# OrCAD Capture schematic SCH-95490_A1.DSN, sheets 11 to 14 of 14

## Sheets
11 11 QSPI FLASH & SENSOR: size C
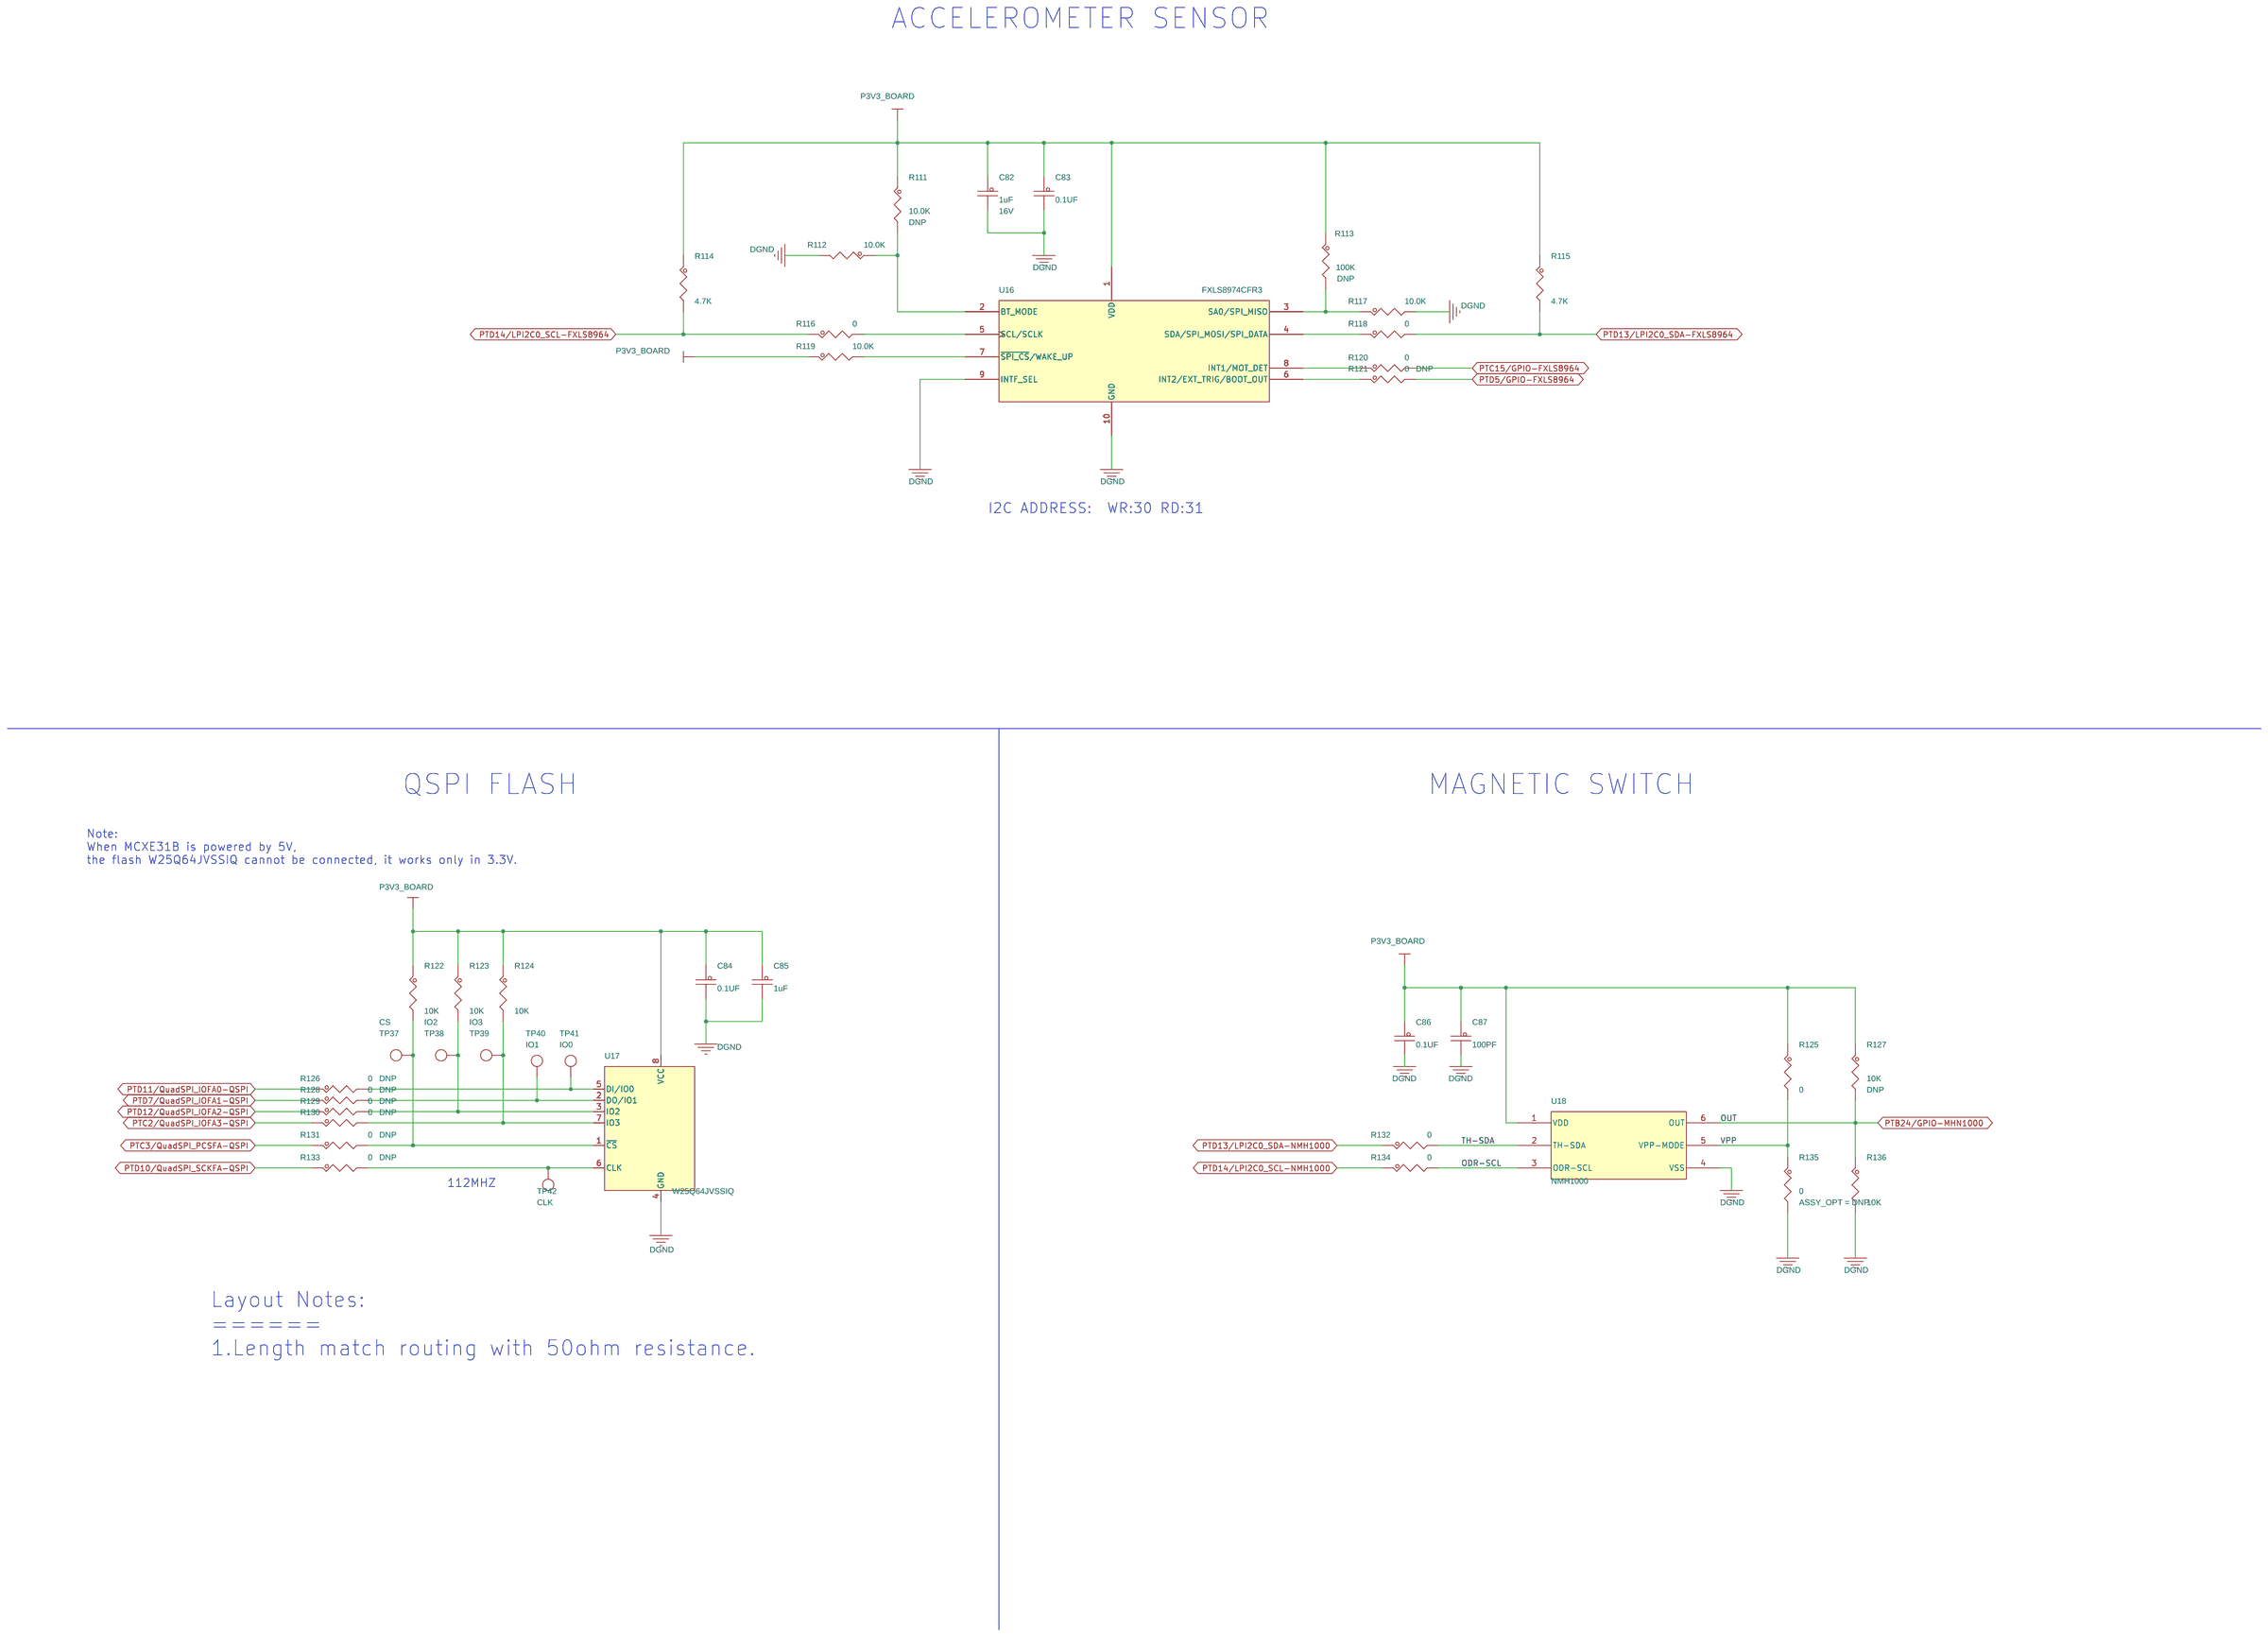
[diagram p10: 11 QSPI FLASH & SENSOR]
12 12 SWITCH & LED: size C
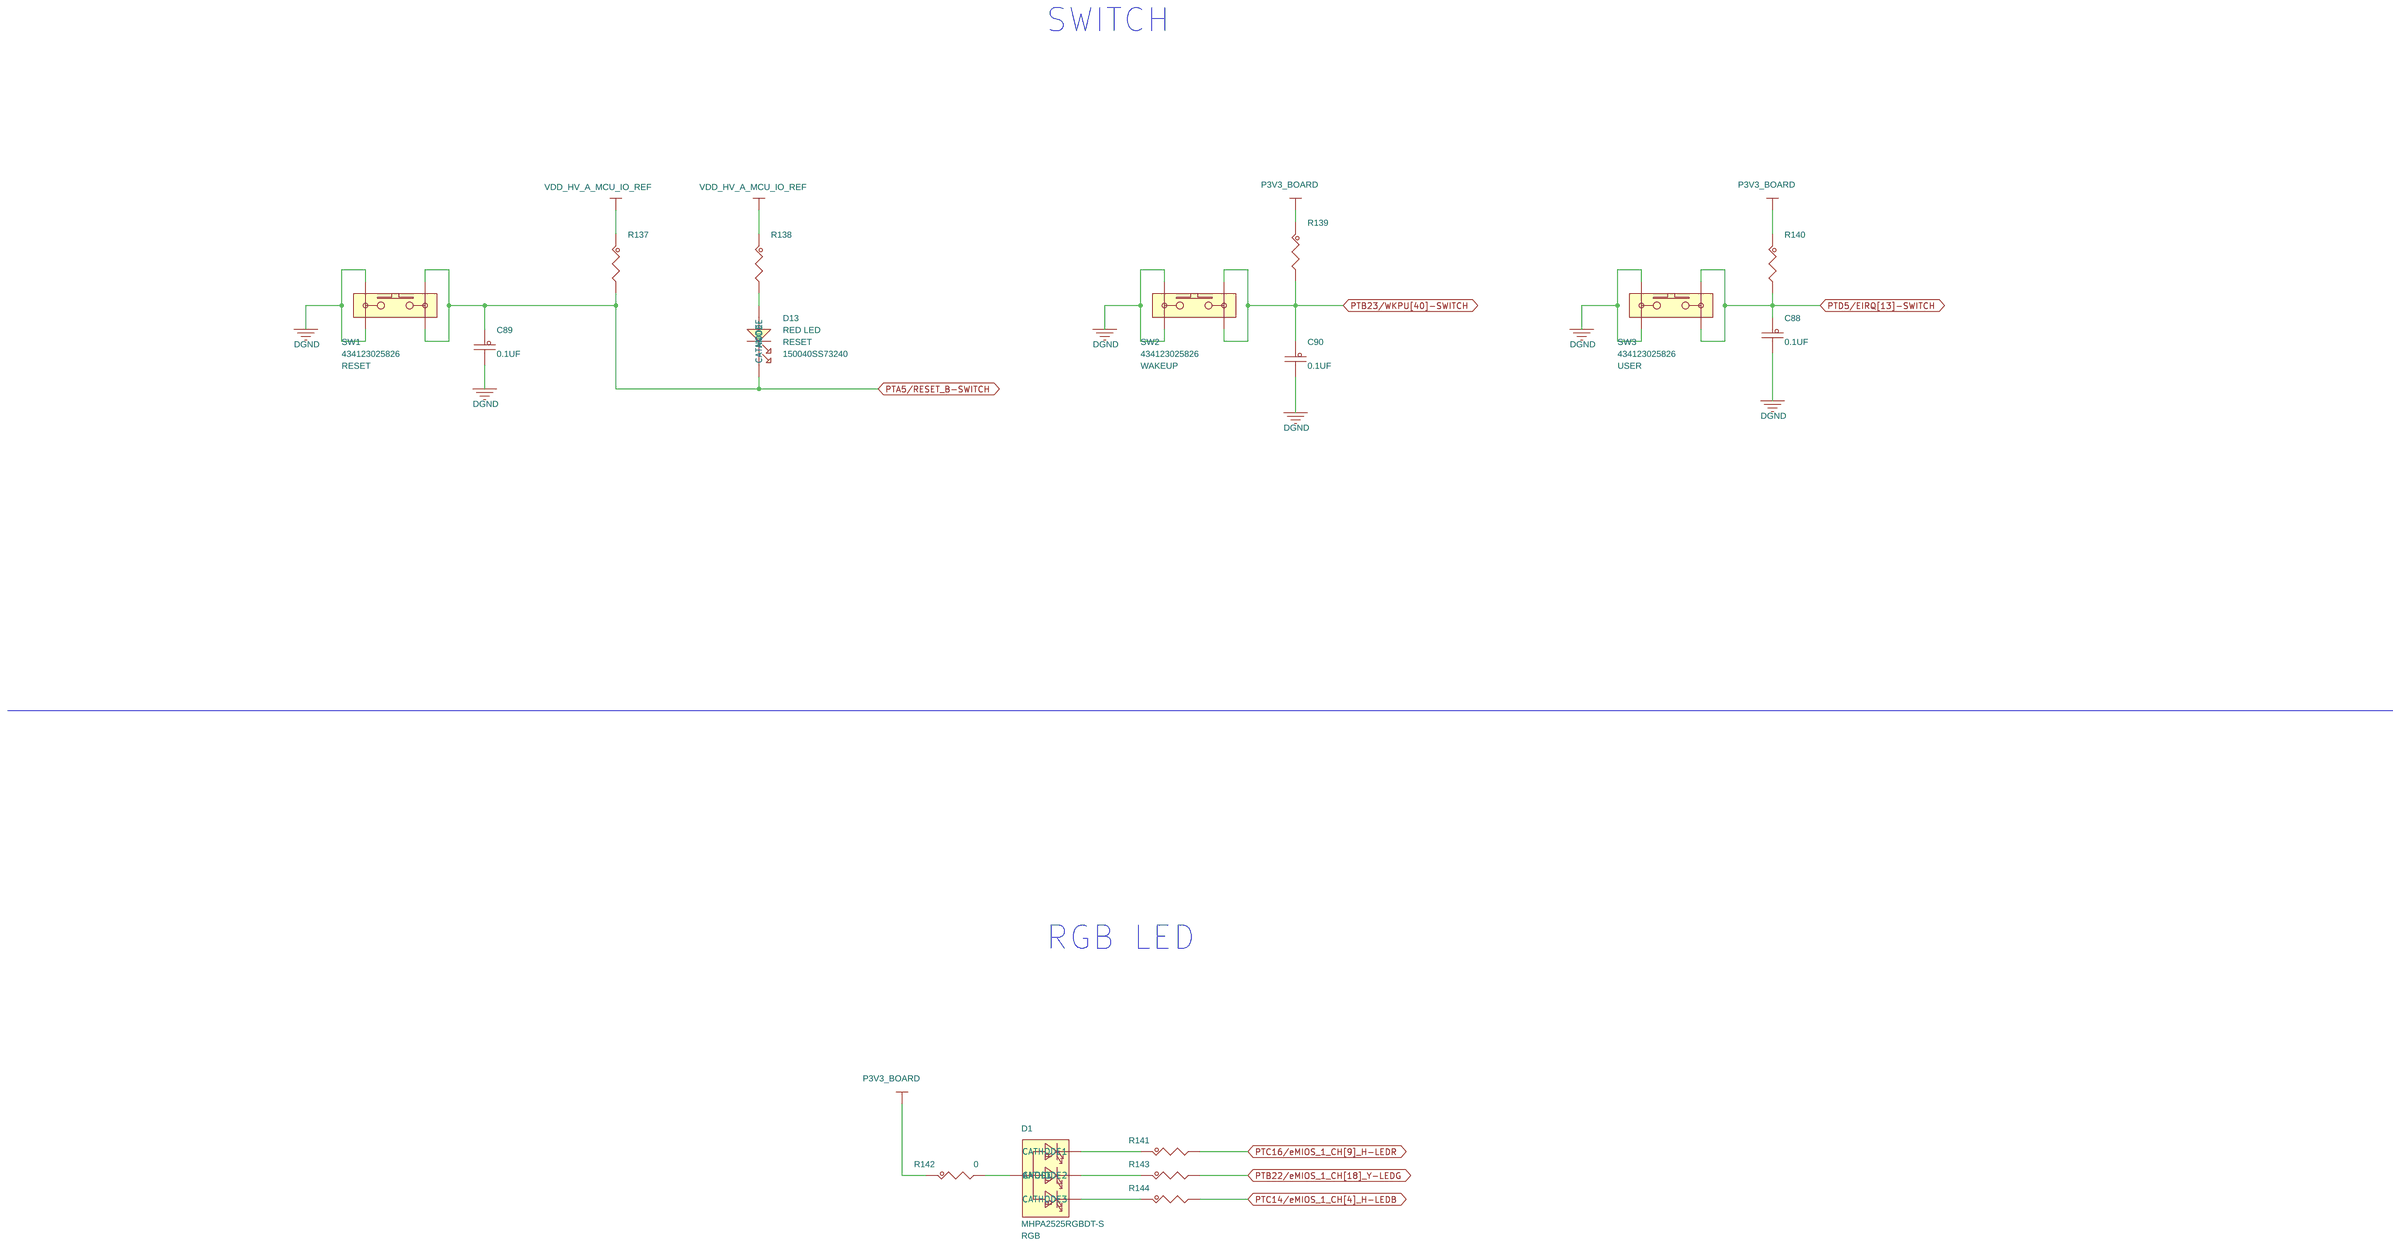
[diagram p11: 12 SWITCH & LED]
13 13 HEADERS: size C
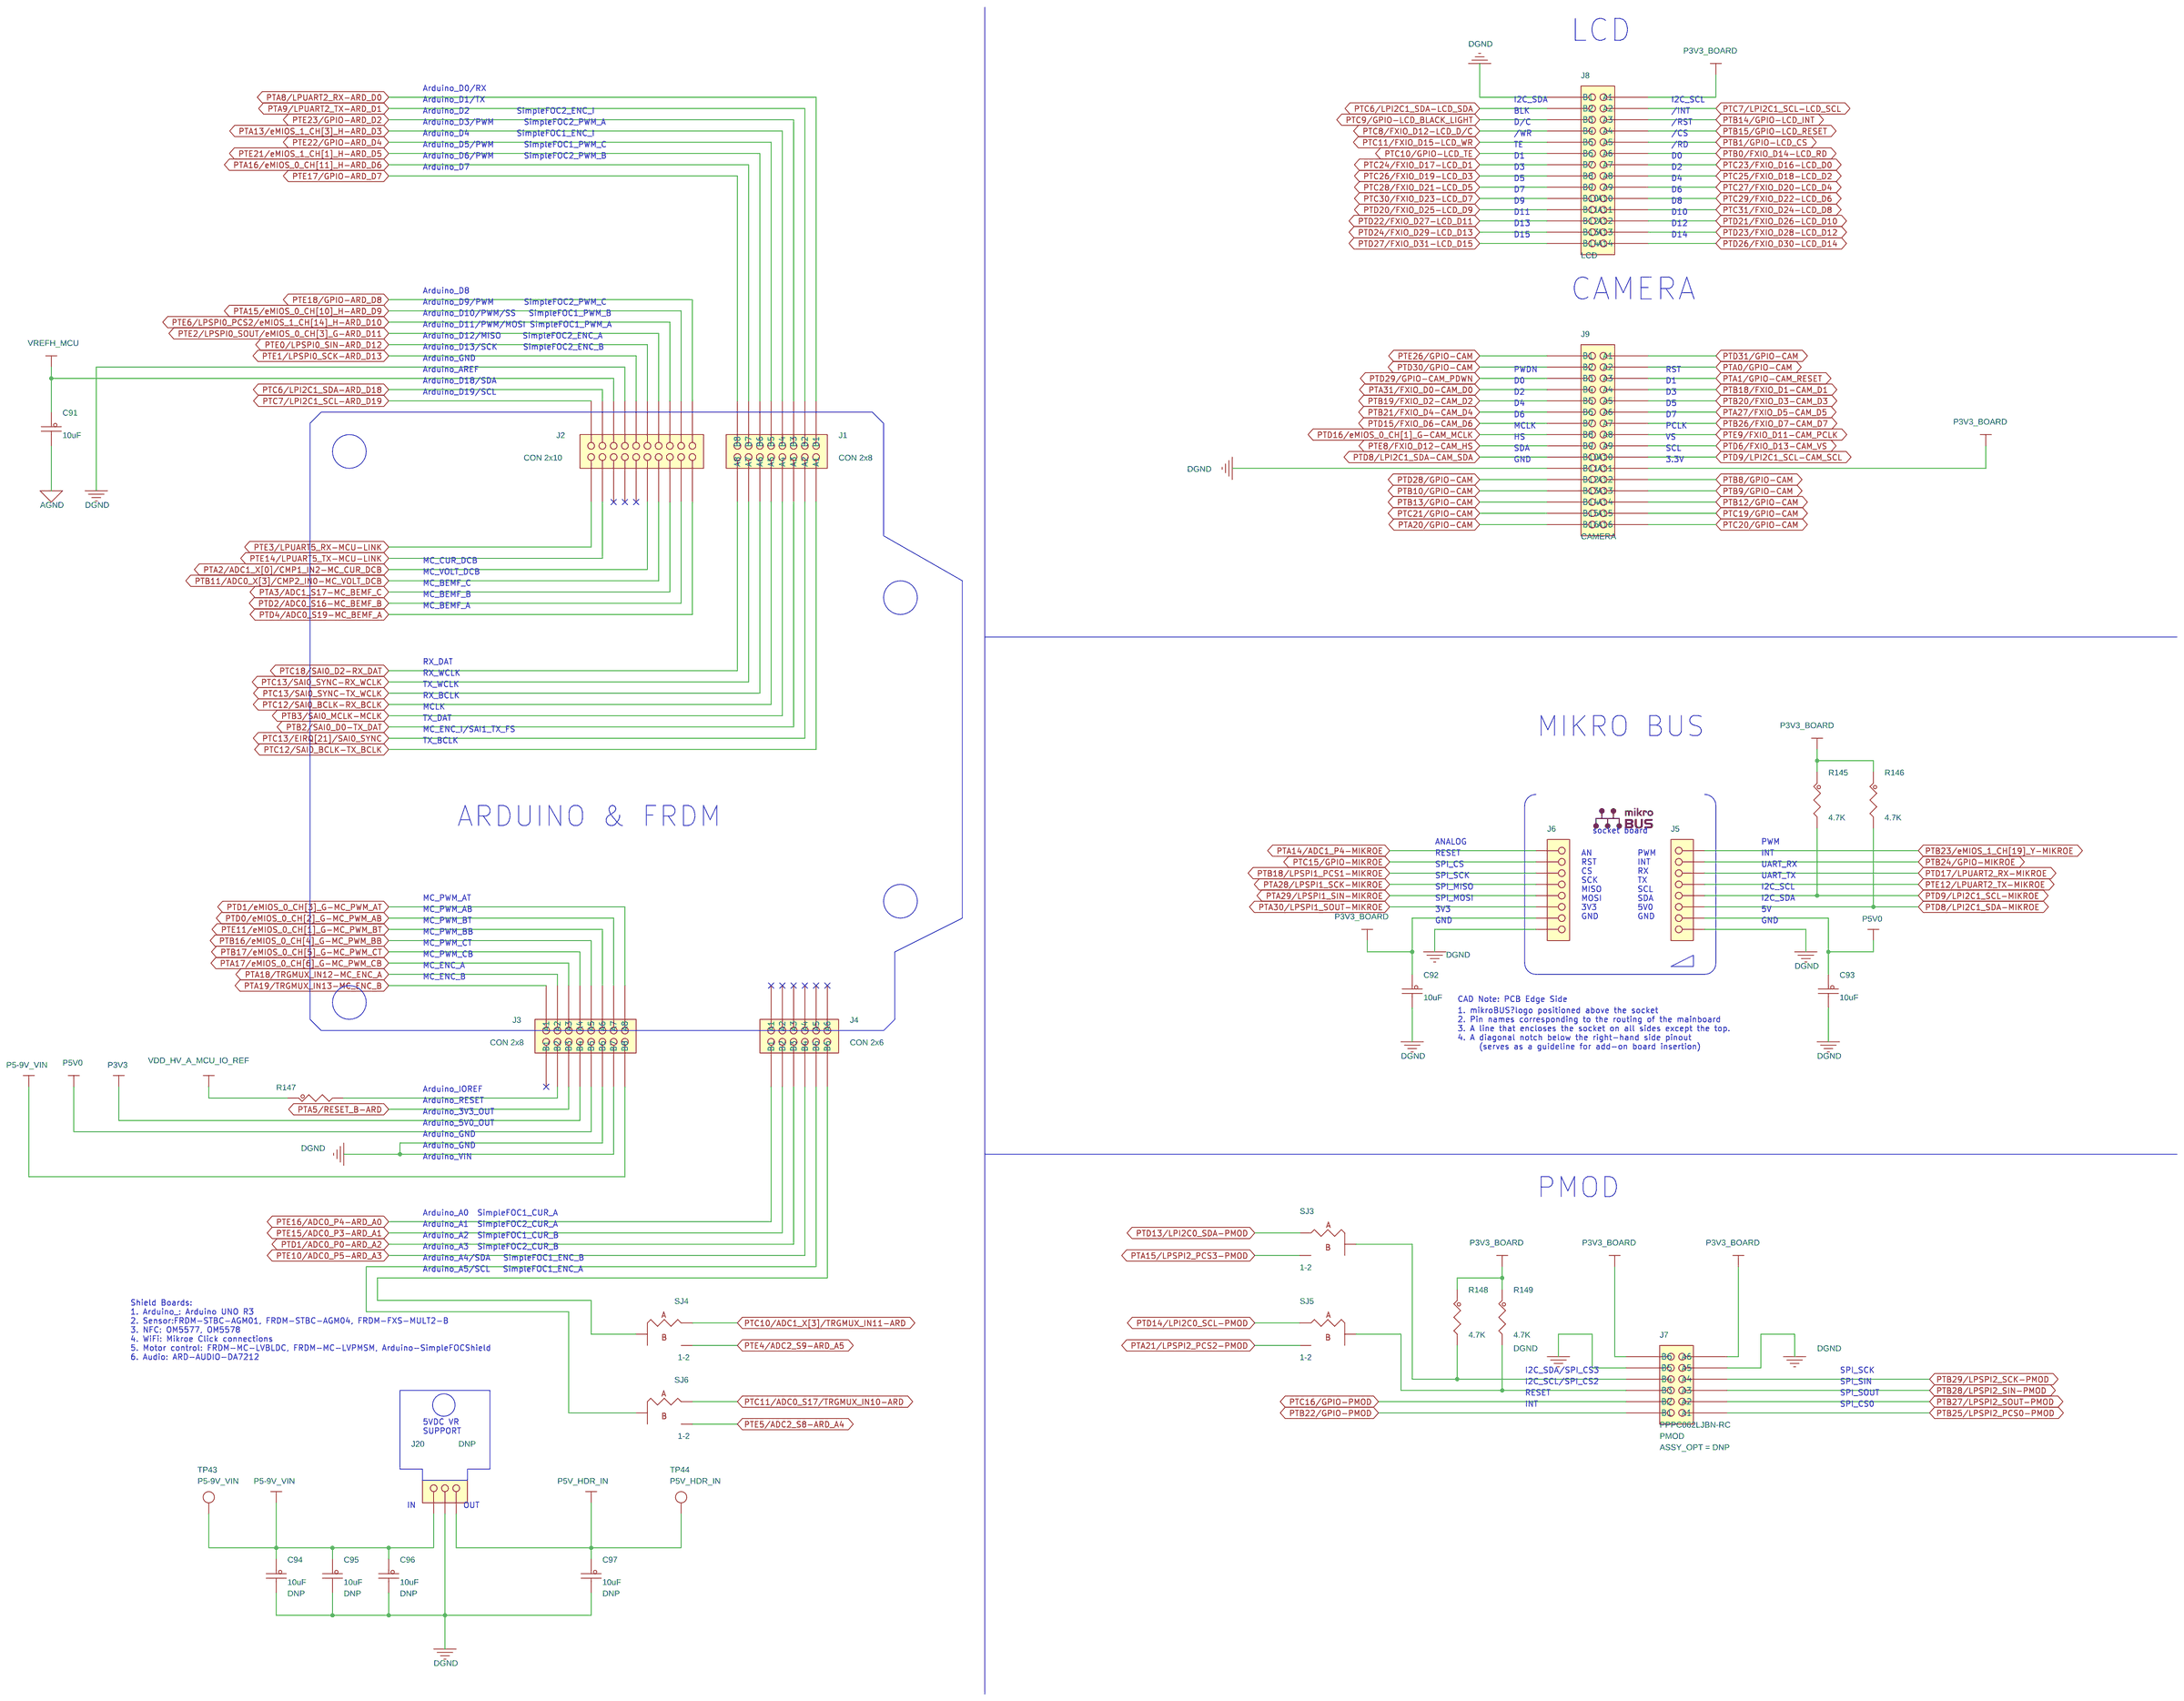
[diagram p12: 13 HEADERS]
14 14 APPENDIX JUMPER/DNP
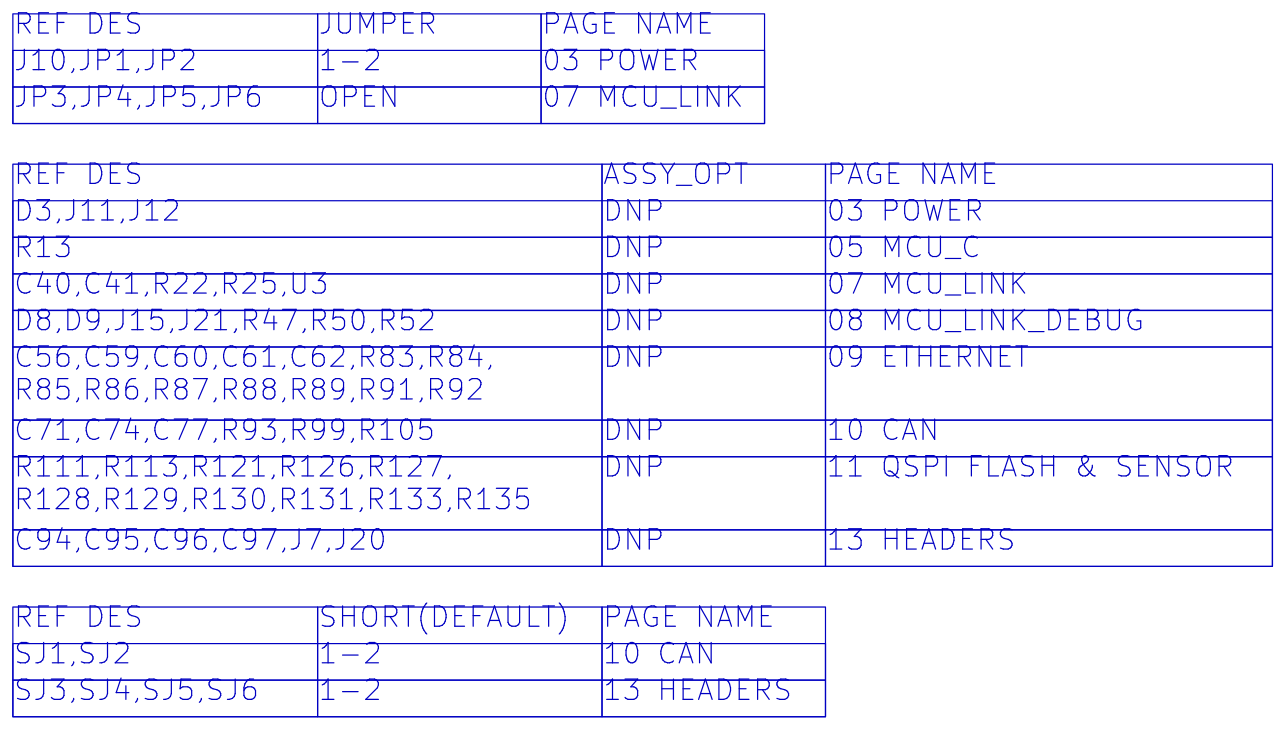
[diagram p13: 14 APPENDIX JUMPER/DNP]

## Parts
sheet 11 QSPI FLASH & SENSOR
C82  1uF  [CC0402_25]
C83  0.1UF  [CC0402_25]
C84  0.1UF  [CC0402_25]
C85  1uF  [CC0402_25]
C86  0.1UF  [CC0402_25]
C87  100PF  [CC0402_25]
R111  10.0K  [RC0402_25]
R112  10.0K  [RC0402_25]
R113  100K  [RC0402_25]
R114  4.7K  [RC0402_25]
R115  4.7K  [RC0402_25]
R116  0  [RC0603_OV]
R117  10.0K  [RC0402_25]
R118  0  [RC0603_OV]
R119  10.0K  [RC0402_25]
R120  0  [RC0603_OV]
R121  0  [RC0603_OV]
R122  10K  [RC0402_25]
R123  10K  [RC0402_25]
R124  10K  [RC0402_25]
R125  0  [RC0603_OV]
R126  0  [RC0603_OV]
R127  10K  [RC0402_25]
R128  0  [RC0603_OV]
R129  0  [RC0603_OV]
R130  0  [RC0603_OV]
R131  0  [RC0603_OV]
R132  0  [RC0603_OV]
R133  0  [RC0603_OV]
R134  0  [RC0603_OV]
R135  0  [RC0603_OV]
R136  10K  [RC0402_25]
TP37  TPAD_030  [TPAD_030]
TP38  TPAD_030  [TPAD_030]
TP39  TPAD_030  [TPAD_030]
TP40  TPAD_030  [TPAD_030]
TP41  TPAD_030  [TPAD_030]
TP42  TPAD_030  [TPAD_030]
U16  FXLS8974CFR3  [DFN_10_0P4_2X2]
U17  W25Q64JVSSIQ  [so8_w]
U18  NMH1000  [dfn6_0p5_1p4sq]
sheet 12 SWITCH & LED
C88  0.1UF  [CC0402_25]
C89  0.1UF  [CC0402_25]
C90  0.1UF  [CC0402_25]
D1  RGB  [led4_2p7x2p6_sm]
D13  RED LED  [led_1p1_1p1x0p6_sm]
R137  10K  [RC0402_25]
R138  470  [RC0402_25]
R139  10K  [RC0402_25]
R140  10K  [RC0402_25]
R141  470  [RC0402_25]
R142  0  [RC0603_OV]
R143  470  [RC0402_25]
R144  470  [RC0402_25]
SW1  SW SPST NO  [sw4_4p15_4p2x3p2_sm]
SW2  SW SPST NO  [sw4_4p15_4p2x3p2_sm]
SW3  SW SPST NO  [sw4_4p15_4p2x3p2_sm]
sheet 13 HEADERS
C91  10uF  [CC0603_OV]
C92  10uF  [CC0603_OV]
C93  10uF  [CC0603_OV]
C94  10uF  [CC0603_OV]
C95  10uF  [CC0603_OV]
C96  10uF  [CC0603_OV]
C97  10uF  [CC0603_OV]
J1  CON 2x8  [con_2x8_skt_100_th]
J2  CON 2x10  [con_skt2x10_th]
J3  CON 2x8  [con_2x8_skt_100_th]
J4  CON 2x6  [con_skt2x6_th_126l]
J5  SKT_1X8  [con_1x8_skt_2p54_th_126l]
J6  SKT_1X8  [con_1x8_skt_2p54_th_126l]
J7  PPPC062LJBN-RC  [skt2x6_100_th_ra]
J8  CON 2x14  [con_skt2x14_th_126l]
J9  CON 2x16  [con_skt_32f_100_th]
J20  HDR_1X3  [HDR103]
R145  4.7K  [RC0402_25]
R146  4.7K  [RC0402_25]
R147  470  [RC0402_25]
R148  4.7K  [RC0402_25]
R149  4.7K  [RC0402_25]
SJ3  3 PIN 0402 JUMPER  [3pin_0402x2_a]
SJ4  3 PIN 0402 JUMPER  [3pin_0402x2_a]
SJ5  3 PIN 0402 JUMPER  [3pin_0402x2_a]
SJ6  3 PIN 0402 JUMPER  [3pin_0402x2_a]
TP43  TEST POINT  [tpad_040-fct]
TP44  TEST POINT  [tpad_040-fct]

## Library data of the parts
C82 C85 = CAP_NP: CAP CER 1.0uF 16V 10% X6S 0402; AGILE_PN: 150-80262; CAD_APPROVED: Yes; FPLIST: CC0402_25,CC0402_HD,0402_CC,capc0402_l; HEIGHT: 0.55; MFG_NAME01: MURATA; MFG_PN01: GRM155C81C105KE11D; ROHS: Yes; Rated Voltage: 16V; Temp Range: -55C to +105C; Tolerance: 10%; VOLTAGE: 16V
C83 C84 C86 C88-C90 = CAP_NP: CAP CER 0.1UF 16V 10% X7R 0402; 3D_Mechanical_Footprint_File: http://fcl.am.freescale.net/ALLEGRO/step/cc0402_25.STEP; AGILE_PN: 150-75182; CAD_APPROVED: Yes; FPLIST: CC0402_25,CC0402_HD,0402_CC,CAPC0402_L,cc0402_lamp3; HEIGHT: 0.635mm; MFG_NAME01: Samsung Electro-Mechanics; MFG_PN01: CL05B104KO5NNNC; ROHS: NULL; Rated Voltage: 16V; SIGNAL_MODEL: DEFAULT_CAPACITOR_100000pF_2_1; TOL: 10%; Temp Range: -55C to +125C; Temp_Range: -55°C to +85°C; Tolerance: 10%; VOLTAGE: 16V
C87 = CAP_NP: CAP CER 100pF 16V 10% X7R 0402; AGILE_PN: 150-79188; CAD_APPROVED: Yes; FPLIST: CC0402_25,CC0402_HD,0402_CC,capc0402_l; HEIGHT: 0.56; MFG_NAME01: AVX; MFG_PN01: 0402YC101KAT2A; Package Size: 0402; Package Type: 7" Reel; ROHS: Yes; Rated Voltage: 16V; TOL: 5%; Temp Range: -55C to +125C; Tolerance: 10%; VOLTAGE: 50V
R111 = RES: RES MF 10.0K 1/16W 1% 0402; AGILE_PN: 470-80574; ASSY_OPT: DNP; CAD_APPROVED: Yes; FPLIST: RC0402_25,RC0402_HD,0402_CC; HEIGHT: 0.4; MFG_NAME01: BOURNS; MFG_PN01: CR0402-FX-1002GLF; ROHS: Yes; Tolerance: 1%
R112 R117 R119 = RES: RES MF 10.0K 1/16W 1% 0402; AGILE_PN: 470-80574; CAD_APPROVED: Yes; FPLIST: RC0402_25,RC0402_HD,0402_CC; HEIGHT: 0.4; MFG_NAME01: BOURNS; MFG_PN01: CR0402-FX-1002GLF; ROHS: Yes; Tolerance: 1%
R113 = RES: RES MF 100K 1/16W 1% 0402; AGILE_PN: 470-76240; ASSY_OPT: DNP; CAD_APPROVED: Yes; FPLIST: RC0402_25,RC0402_HD,0402_CC; HEIGHT: 0.4; MFG_NAME01: VISHAY INTERTECHNOLOGY; MFG_PN01: CRCW0402100KFKEDC; ROHS: Yes; Tolerance: 1%
R114 R115 R145 R146 R148 R149 = RES: RES MF 4.7K 1/16W 5% 0402; AGILE_PN: 470-75626; CAD_APPROVED: Yes; FPLIST: RC0402_25,RC0402_HD,0402_CC,RC0402_X2; HEIGHT: 0.41; MFG_NAME01: BOURNS; MFG_PN01: CR0402-JW-472GLF; Pkg: 0402; ROHS: NULL; Tolerance: 5%
R116 R118 R120 R125 R132 R134 = RES: RES MF ZERO OHM 1/10W -- 0603; AGILE_PN: 470-80866; CAD_APPROVED: Yes; FPLIST: RC0603_OV,RC0603,R603-X2,r603-x2_b,0603_CC,IND_0603HP_NSP,CC0603_OV_NSP; HEIGHT: 0.6; MFG_NAME01: VISHAY; MFG_PN01: CRCW06030000Z0EAC; ROHS: NULL; Temp Range: –55 °C to +155 °C; VOLTAGE: 1/16W
R121 R135 = RES: RES MF ZERO OHM 1/10W -- 0603; AGILE_PN: 470-80866; ASSY_OPT: DNP; CAD_APPROVED: Yes; FPLIST: RC0603_OV,RC0603,R603-X2,r603-x2_b,0603_CC,IND_0603HP_NSP,CC0603_OV_NSP; HEIGHT: 0.6; MFG_NAME01: VISHAY; MFG_PN01: CRCW06030000Z0EAC; ROHS: NULL; Temp Range: –55 °C to +155 °C; VOLTAGE: 1/16W
R122-R124 = RES: RES MF 10K 1/16W 5% 0402; AGILE_PN: 470-75557; CAD_APPROVED: Yes; FPLIST: RC0402_25,RC0402_HD,0402_CC; HEIGHT: 0.4MM; MFG_NAME01: BOURNS; MFG_PN01: CR0402-JW-103GLF; ROHS: NULL; SIGNAL_MODEL: DEFAULT_RESISTOR_10000OHM_2_1; TOL: 1%; Temp_Range: –55 °C to +155 °C; Tolerance: 5%
R126 R128-R131 R133 = RES: RES MF ZERO OHM 1/10W -- 0603; AGILE_PN: 470-80866; ASSY_OPT: DNP; CAD_APPROVED: Yes; FPLIST: RC0603_OV,RC0603,R603-X2,r603-x2_b,0603_CC,IND_0603HP_NSP,CC0603_OV_NSP; HEIGHT: 0.6; MFG_NAME01: VISHAY; MFG_PN01: CRCW06030000Z0EAC; ROHS: NULL; Temp Range: –55 °C to +155 °C
R127 = RES: RES MF 10K 1/16W 5% 0402; AGILE_PN: 470-75557; ASSY_OPT: DNP; CAD_APPROVED: Yes; FPLIST: RC0402_25,RC0402_HD,0402_CC; HEIGHT: 0.4MM; MFG_NAME01: BOURNS; MFG_PN01: CR0402-JW-103GLF; ROHS: NULL; Tolerance: 5%
R136 = RES: RES MF 10K 1/16W 5% 0402; AGILE_PN: 470-75557; CAD_APPROVED: Yes; FPLIST: RC0402_25,RC0402_HD,0402_CC; HEIGHT: 0.4MM; MFG_NAME01: BOURNS; MFG_PN01: CR0402-JW-103GLF; ROHS: NULL; Tolerance: 5%
TP37 = TESTLOOP: TEST POINT PAD 30MIL DIA SMT, NO PART TO ORDER; 3D_Mechanical_Footprint_File: http://fcl.am.freescale.net/ALLEGRO/step/tpad_030.STEP; AGILE_PN: 211-76642; CAD_APPROVED: Yes; HEIGHT: 0.1; MFG_NAME01: NOTACOMPONENT; MFG_PN01: NOTACOMPONENT; ROHS: Yes; SILK: CS
TP38 = TESTLOOP: TEST POINT PAD 30MIL DIA SMT, NO PART TO ORDER; 3D_Mechanical_Footprint_File: http://fcl.am.freescale.net/ALLEGRO/step/tpad_030.STEP; AGILE_PN: 211-76642; CAD_APPROVED: Yes; HEIGHT: 0.1; MFG_NAME01: NOTACOMPONENT; MFG_PN01: NOTACOMPONENT; ROHS: Yes; SILK: IO2
TP39 = TESTLOOP: TEST POINT PAD 30MIL DIA SMT, NO PART TO ORDER; 3D_Mechanical_Footprint_File: http://fcl.am.freescale.net/ALLEGRO/step/tpad_030.STEP; AGILE_PN: 211-76642; CAD_APPROVED: Yes; HEIGHT: 0.1; MFG_NAME01: NOTACOMPONENT; MFG_PN01: NOTACOMPONENT; ROHS: Yes; SILK: IO3
TP40 = TESTLOOP: TEST POINT PAD 30MIL DIA SMT, NO PART TO ORDER; 3D_Mechanical_Footprint_File: http://fcl.am.freescale.net/ALLEGRO/step/tpad_030.STEP; AGILE_PN: 211-76642; CAD_APPROVED: Yes; HEIGHT: 0.1; MFG_NAME01: NOTACOMPONENT; MFG_PN01: NOTACOMPONENT; ROHS: Yes; SILK: IO1
TP41 = TESTLOOP: TEST POINT PAD 30MIL DIA SMT, NO PART TO ORDER; 3D_Mechanical_Footprint_File: http://fcl.am.freescale.net/ALLEGRO/step/tpad_030.STEP; AGILE_PN: 211-76642; CAD_APPROVED: Yes; HEIGHT: 0.1; MFG_NAME01: NOTACOMPONENT; MFG_PN01: NOTACOMPONENT; ROHS: Yes; SILK: IO0
TP42 = TESTLOOP: TEST POINT PAD 30MIL DIA SMT, NO PART TO ORDER; 3D_Mechanical_Footprint_File: http://fcl.am.freescale.net/ALLEGRO/step/tpad_030.STEP; AGILE_PN: 211-76642; CAD_APPROVED: Yes; HEIGHT: 0.1; MFG_NAME01: NOTACOMPONENT; MFG_PN01: NOTACOMPONENT; ROHS: Yes; SILK: CLK
U16 = FXLS8962AF_DFN10: IC ACCELEROMETER 3-AXIS 12BIT 1.71-3.6V AEC-Q100 DFN10; 3D_Mechanical_Footprint_File: http://fcl.am.freescale.net/ALLEGRO/step/dfn_10_0p4_2x2.STEP; AGILE_PN: TMP-CIP-7425; CAD_APPROVED: Yes; HEIGHT: 1; MFG_NAME01: NXP SEMICONDUCTORS; PRE_APN: 312-83141; ROHS: Yes; Temp Range: -40  °C to +105 °C
U17 = W25Q64JV_SOIC_8P_B: IC MEM SERIAL FLASH DUAL/QUAD SPI 64MBIT 2.7-3.6V SOIC8; AGILE_PN: 342-00710; CAD_APPROVED: Yes; HEIGHT: 2.16; MFG_NAME01: WINBOND ELECTRONICS CORP; ROHS: Yes; Temp Range: ¨C40C to +85C; VOLTAGE: 2.7-3.6V
U18 = NMH1000_6P: IC SENSOR Z-AXIC MAGNETIC SW 1.2-3.6V PDFN6; 3D_Mechanical_Footprint_File: http://fcl.am.freescale.net/ALLEGRO/step/dfn6_0p5_1p4sq.STEP; AGILE_PN: TMP-CIP-6445; CAD_APPROVED: Yes; HEIGHT: 0.9; MFG_NAME01: NXP SEMICONDUCTORS; PRE_APN: 312-83057; Package Size: 1.4x1.4x0.9 mm; ROHS: Yes; Temp Range: -40°C  to +85°C; VOLTAGE: 1.2-3.6V
D1 = LRTBR48G_4P: LED RED/GRN/BL TRI 20/20/20MA SMT; 3D_Mechanical_Footprint_File: http://fcl.am.freescale.net/ALLEGRO/step/led4_2p7x2p6_sm.step; AGILE_PN: 370-76899; CAD_APPROVED: YES; HEIGHT: 2.14mm; MFG_NAME01: Lianyungang Meihua Electronics Technology Co.,Ltd; MFG_PN01: MHPA2525RGBDT-S; Temp Range: -40 to +100
D13 = LED: LED RED SGL 30mA 5V 0402; 3D_Mechanical_Footprint_File: http://fcl.am.freescale.net/ALLEGRO/step/led_1p1_1p1x0p6_sm.STEP; AGILE_PN: 370-77428; CAD_APPROVED: YES; HEIGHT: 0.5; MFG_NAME01: Wurth Electronik GmbH & Co. KG (PCB); MFG_PN01: 150040SS73240; SILK: RESET; Temp Range: -40° C to + 85° C
R137 R139 R140 = RES: RES MF 10K 1/16W 5% 0402; AGILE_PN: 470-75557; CAD_APPROVED: Yes; FPLIST: RC0402_25,RC0402_HD,0402_CC; HEIGHT: 0.4MM; MFG_NAME01: BOURNS; MFG_PN01: CR0402-JW-103GLF; ROHS: NULL; SIGNAL_MODEL: DEFAULT_RESISTOR_10000OHM_2_1; TOL: 5%; Temp_Range: –55 °C to +155 °C; Tolerance: 5%
R138 R141 R143 R144 R147 = RES: RES MF 470 OHM 1/16W 5% 0402; AGILE_PN: 470-30315; CAD_APPROVED: Yes; FPLIST: RC0402_25,RC0402_HD,0402_CC; HEIGHT: 0.45; MFG_NAME01: PANASONIC; MFG_PN01: ERJ2GEJ471X; ROHS: Yes; SIGNAL_MODEL: DEFAULT_RESISTOR_430.000000OHM_2_1; TOL: 1%; Temp_Range: -55&#8451; to 155&#8451;; Tolerance: 5%
R142 = RES: RES MF ZERO OHM 1/10W -- 0603; AGILE_PN: 470-80866; CAD_APPROVED: Yes; FPLIST: RC0603_OV,RC0603,R603-X2,r603-x2_b,0603_CC,IND_0603HP_NSP,CC0603_OV_NSP; HEIGHT: 0.6; MFG_NAME01: VISHAY; MFG_PN01: CRCW06030000Z0EAC; ROHS: NULL; Temp Range: –55 °C to +155 °C
SW1 = SW_PSHBT_SPST_2: SW SP PB 50mA 16V SMT; 3D_Mechanical_Footprint_File: http://fcl.am.freescale.net/ALLEGRO/step/sw4_4p15_4p2x3p2_sm.STEP; AGILE_PN: 510-78653; CAD_APPROVED: Yes; HEIGHT: 2.60; MFG_NAME01: WURTH ELEKTRONIK EISOS GMBH & CO. KG (ELECTRONIC & ELECTROMEHANICAL COMP); MFG_PN01: 434123025826; ROHS: Yes; SILK: RESET; Temp Range: -40C to +85C
SW2 = SW_PSHBT_SPST_2: SW SP PB 50mA 16V SMT; 3D_Mechanical_Footprint_File: http://fcl.am.freescale.net/ALLEGRO/step/sw4_4p15_4p2x3p2_sm.STEP; AGILE_PN: 510-78653; CAD_APPROVED: Yes; HEIGHT: 2.60; MFG_NAME01: WURTH ELEKTRONIK EISOS GMBH & CO. KG (ELECTRONIC & ELECTROMEHANICAL COMP); MFG_PN01: 434123025826; ROHS: Yes; SILK: WAKEUP; Temp Range: -40C to +85C
SW3 = SW_PSHBT_SPST_2: SW SP PB 50mA 16V SMT; 3D_Mechanical_Footprint_File: http://fcl.am.freescale.net/ALLEGRO/step/sw4_4p15_4p2x3p2_sm.STEP; AGILE_PN: 510-78653; CAD_APPROVED: Yes; HEIGHT: 2.60; MFG_NAME01: WURTH ELEKTRONIK EISOS GMBH & CO. KG (ELECTRONIC & ELECTROMEHANICAL COMP); MFG_PN01: 434123025826; ROHS: Yes; SILK: USER; Temp Range: -40C to +85C
C91-C93 = CAP_NP: CAP CER 10uF 25V 20% X5R 0603; AGILE_PN: 150-79272; CAD_APPROVED: Yes; FPLIST: CC0603_OV,CC0603,0603_cc_tol; HEIGHT: 1; MFG_NAME01: MURATA; MFG_PN01: GRM188R61E106MA73D; Package Size: 0603; ROHS: Yes; Rated Voltage: 25V; Temp Range: -55C to +85C; Tolerance: 20%
C94-C97 = CAP_NP: CAP CER 10uF 25V 20% X5R 0603; AGILE_PN: 150-79272; ASSY_OPT: DNP; CAD_APPROVED: Yes; FPLIST: CC0603_OV,CC0603,0603_cc_tol; HEIGHT: 1; MFG_NAME01: MURATA; MFG_PN01: GRM188R61E106MA73D; Package Size: 0603; ROHS: Yes; Rated Voltage: 25V; Temp Range: -55C to +85C; Tolerance: 20%
J1 J3 = CONN_HDR_8X2: CON 2X8 SKT SHRD TH 100MIL CTR 345H AU 126L; 3D_Mechanical_Footprint_File: http://fcl.am.freescale.net/ALLEGRO/step/con_2x8_skt_100_th.STEP; AGILE_PN: 210-81775; CAD_APPROVED: Yes; HEIGHT: 8.75mm; MFG_NAME01: ANYTRONIC CORPORATION LIMITED; MFG_PN01: 08010S31611-29RF; ROHS: NULL; Temp Range: -40 to +105C
J2 = CONN_HDR_10X2: CON 2X10 SKT SHRD TH 100MIL CTR 345H AU 126L; 3D_Mechanical_Footprint_File: http://fcl.am.freescale.net/ALLEGRO/step/con_skt2x10_th.STEP; AGILE_PN: 210-81776; CAD_APPROVED: Yes; HEIGHT: 8.88mm; MFG_NAME01: ANYTRONIC CORPORATION LIMITED; MFG_PN01: 08010S32011-29RF; ROHS: NULL; Temp Range: -40 to +105C
J4 = CONN_HDR_6X2: CON 2X6 SKT SHRD TH 100MIL CTR 345H AU 126L; 3D_Mechanical_Footprint_File: http://fcl.am.freescale.net/ALLEGRO/step/con_skt2x6_th_126l.STEP; AGILE_PN: 210-81774; CAD_APPROVED: Yes; FPLIST: con_skt2x6_th_126l,con_skt2x6_th; HEIGHT: 8.75mm; MFG_NAME01: ANYTRONIC CORPORATION LIMITED; MFG_PN01: 08010S31211-29RF; ROHS: NULL; Temp Range: -40 to +105C
J5 J6 = CONN_HDR_8X1: CON 1X8 SKT TH 100MIL SP 344H AU 118L; 3D_Mechanical_Footprint_File: http://fcl.am.freescale.net/ALLEGRO/step/con_1x8_skt_2p54_th_126l.STEP; AGILE_PN: 210-81617; CAD_APPROVED: Yes; FPLIST: con_1x8_skt_2p54_th_126l,con_1x8_skt_2p54_th; HEIGHT: 8.75mm; MFG_NAME01: ANYTRONIC CORPORATION LIMITED; MFG_PN01: 08001S3 0811-29RF; ROHS: NULL; Temp Range: -40°C to +105°C
J7 = CONN_HDR_6X2: CON 2X6 SKT RA TH 100MIL CTR 206H AU 124L; 3D_Mechanical_Footprint_File: http://fcl.am.freescale.net/ALLEGRO/step/skt2x6_100_th_ra.step; AGILE_PN: 210-80998; ASSY_OPT: DNP; CAD_APPROVED: Yes; HEIGHT: 5.28; MFG_NAME01: SULLINS ELECTRONICS CORP; ROHS: Yes; SILK: PMOD
J8 = CONN_HDR_14X2: CON 2X14 SKT SHRD TH 100MIL CTR 345H AU 126L; 3D_Mechanical_Footprint_File: http://fcl.am.freescale.net/ALLEGRO/step/con_skt2x14_th_126l.STEP; AGILE_PN: 210-83442; CAD_APPROVED: Yes; HEIGHT: 8.75mm; MFG_NAME01: ANYTRONIC CORPORATION LIMITED; MFG_PN01: 08010S32811-29RF; ROHS: NULL; SILK: LCD; Temp Range: -40 to +105C
J9 = CONN_HDR_16X2: CON 2X16 SKT SHRD TH 100MIL CTR 345H AU 126L; 3D_Mechanical_Footprint_File: http://fcl.am.freescale.net/ALLEGRO/step/con_skt_32f_100_th.STEP; AGILE_PN: 210-83440; CAD_APPROVED: Yes; HEIGHT: 8.75mm; MFG_NAME01: ANYTRONIC CORPORATION LIMITED; MFG_PN01: 08010S33211-29RF; ROHS: NULL; SILK: CAMERA; Temp Range: -40 to +105C
J20 = CONN_HDR_3X1: HDR 1X3 TH 100MIL SP 330H AU 98L; 3D_Mechanical_Footprint_File: http://fcl.am.freescale.net/ALLEGRO/step/hdr103_330h.STEP; AGILE_PN: 210-75442; ASSY_OPT: DNP; CAD_APPROVED: Yes; HEIGHT: 8.59; MFG_NAME01: SAMTEC; MFG_PN01: HTSW-103-07-S-S; PRIORITY_PN: 028-00700; Package Type: HEADER; ROHS: NULL; Temp Range: -55°C to +125°C
SJ3-SJ6 = RES_3PIN_C: SOLDER BLOB JUMPER 3PIN 1-2 SHORT 0402 - NO PART TO ORDER; AGILE_PN: 470-83592; CAD_APPROVED: Yes; HEIGHT: 0.1016; MFG_NAME01: NA; ROHS: Yes; SHORT(DEFAULT): 1-2
TP43 = TESTLOOP: TEST POINT PAD 40MIL DIA SMT, NO PART TO ORDER; AGILE_PN: 211-10189; CAD_APPROVED: yes; HEIGHT: 0.1MM; MFG_NAME01: NO PART TO ORDER; MFG_PN01: NO PART TO ORDER; ROHS: NULL; SILK: P5-9V_VIN
TP44 = TESTLOOP: TEST POINT PAD 40MIL DIA SMT, NO PART TO ORDER; AGILE_PN: 211-10189; CAD_APPROVED: yes; HEIGHT: 0.1MM; MFG_NAME01: NO PART TO ORDER; MFG_PN01: NO PART TO ORDER; ROHS: NULL; SILK: P5V_HDR_IN

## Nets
AGND: C91.2 ; also on sheet 5
DGND: C82.2 C83.2 C84.2 C85.2 C86.2 C87.2 C88.2 C89.2 C90.2 C92.2 C93.2 C94.2 C95.2 C96.2 C97.2 J2.14 J3.12(B6) J3.14(B7) J5.8 J6.8 J7.9(A5) J7.10(B5) J8.2(B1) J9.22(B11) J20.2 R112.2 R117.2 R135.2 R136.2 SW1.1 SW1.2 SW2.1 SW2.2 SW3.1 SW3.2 U16.9(INTF_SEL) U16.10(GND) U17.4(GND) U18.4(VSS) ; also on sheet 3 5 7 8 9 10
P3V3: J3.8(B4) ; also on sheet 3
P3V3_BOARD: C82.1 C83.1 C84.1 C85.1 C86.1 C87.1 C92.1 J6.7 J7.11(A6) J7.12(B6) J8.1(A1) J9.21(A11) R111.1 R113.1 R114.1 R115.1 R119.1 R122.1 R123.1 R124.1 R125.1 R127.1 R139.1 R140.1 R142.1 R145.1 R146.1 R148.1 R149.1 U16.1(VDD) U17.8(VCC) U18.1(VDD) ; also on sheet 3 7 8 9 10
P5V0: C93.1 J3.10(B5) J5.7 ; also on sheet 3 10
P5V_HDR_IN: C97.1 J20.3 TP44.1(Pin1) ; also on sheet 3
VDD_HV_A_MCU_IO_REF: R137.1 R138.1 R147.1 ; also on sheet 3 6 7 8 10
ODR-SCL: R134.2 U18.3(ODR-SCL)
P5-9V_VIN: C94.1 C95.1 C96.1 J3.16(B8) J20.1 TP43.1(Pin1)
PTA0: J9.3(A2) ; also on sheet 4
PTA1: J9.5(A3) ; also on sheet 4
PTA2: J2.9 ; also on sheet 4
PTA3: J2.5 ; also on sheet 4
PTA5: C89.1 D13.C(CATHODE) J3.6(B3) R137.2 SW1.3 SW1.4 ; also on sheet 4 8
PTA8: J1.2(B1) ; also on sheet 4
PTA9: J1.4(B2) ; also on sheet 4
PTA13: J1.8(B4) ; also on sheet 4
PTA14: J6.1 ; also on sheet 4
PTA15: J2.4 SJ3.3 ; also on sheet 4
PTA16: J1.14(B7) ; also on sheet 4
PTA17: J3.5(A3) ; also on sheet 4
PTA18: J3.3(A2) ; also on sheet 4
PTA19: J3.1(A1) ; also on sheet 4
PTA20: J9.32(B16) ; also on sheet 4
PTA21: SJ5.3 ; also on sheet 4
PTA27: J9.11(A6) ; also on sheet 4
PTA28: J6.4 ; also on sheet 4
PTA29: J6.5 ; also on sheet 4
PTA30: J6.6 ; also on sheet 4
PTA31: J9.8(B4) ; also on sheet 4
PTB0: J8.11(A6) ; also on sheet 4
PTB1: J8.9(A5) ; also on sheet 4
PTB2: J1.5(A3) ; also on sheet 4
PTB3: J1.7(A4) ; also on sheet 4
PTB8: J9.23(A12) ; also on sheet 4
PTB9: J9.25(A13) ; also on sheet 4
PTB10: J9.26(B13) ; also on sheet 4
PTB11: J2.7 ; also on sheet 4
PTB12: J9.27(A14) ; also on sheet 4
PTB13: J9.28(B14) ; also on sheet 4
PTB14: J8.5(A3) ; also on sheet 4
PTB15: J8.7(A4) ; also on sheet 4
PTB16: J3.9(A5) ; also on sheet 4
PTB17: J3.7(A4) ; also on sheet 4
PTB18: J6.3 J9.7(A4) ; also on sheet 4
PTB19: J9.10(B5) ; also on sheet 4
PTB20: J9.9(A5) ; also on sheet 4
PTB21: J9.12(B6) ; also on sheet 4
PTB22: J7.2(B1) R143.2 ; also on sheet 4
PTB23: C90.1 J5.1 R139.2 SW2.3 SW2.4 ; also on sheet 4
PTB24: J5.2 R127.2 R136.1 U18.6(OUT) ; also on sheet 4
PTB25: J7.1(A1) ; also on sheet 4
PTB26: J9.13(A7) ; also on sheet 4
PTB27: J7.3(A2) ; also on sheet 4
PTB28: J7.5(A3) ; also on sheet 4
PTB29: J7.7(A4) ; also on sheet 4
PTC2: R130.1 ; also on sheet 4 8 9
PTC3: R131.1 ; also on sheet 4 9
PTC6: J2.18 J8.4(B2) ; also on sheet 4 6
PTC7: J2.20 J8.3(A2) ; also on sheet 4 6
PTC8: J8.8(B4) ; also on sheet 4
PTC9: J8.6(B3) ; also on sheet 4
PTC10: J8.12(B6) SJ4.1 ; also on sheet 4
PTC11: J8.10(B5) SJ6.1 ; also on sheet 4
PTC12: J1.1(A1) J1.9(A5) ; also on sheet 4
PTC13: J1.3(A2) J1.11(A6) J1.13(A7) ; also on sheet 4
PTC14: R144.2 ; also on sheet 4
PTC15: J6.2 R120.2 ; also on sheet 4
PTC16: J7.4(B2) R141.2 ; also on sheet 4
PTC18: J1.15(A8) ; also on sheet 4
PTC19: J9.29(A15) ; also on sheet 4
PTC20: J9.31(A16) ; also on sheet 4
PTC21: J9.30(B15) ; also on sheet 4
PTC23: J8.13(A7) ; also on sheet 4
PTC24: J8.14(B7) ; also on sheet 4
PTC25: J8.15(A8) ; also on sheet 4
PTC26: J8.16(B8) ; also on sheet 4
PTC27: J8.17(A9) ; also on sheet 4
PTC28: J8.18(B9) ; also on sheet 4
PTC29: J8.19(A10) ; also on sheet 4
PTC30: J8.20(B10) ; also on sheet 4
PTC31: J8.21(A11) ; also on sheet 4
PTD0: J3.13(A7) ; also on sheet 4
PTD1: J3.15(A8) J4.6(B3) ; also on sheet 4
PTD2: J2.3 ; also on sheet 4
PTD4: J2.1 ; also on sheet 4
PTD5: C88.1 R121.2 R140.2 SW3.3 SW3.4 ; also on sheet 4
PTD6: J9.17(A9) ; also on sheet 4
PTD7: R128.1 ; also on sheet 4 8 9
PTD8: J5.6 J9.20(B10) R146.2 ; also on sheet 4
PTD9: J5.5 J9.19(A10) R145.2 ; also on sheet 4
PTD10: R133.1 ; also on sheet 4 8
PTD11: R126.1 ; also on sheet 4 8 9
PTD12: R129.1 ; also on sheet 4 8 9
PTD13: R115.2 R118.2 R132.1 SJ3.1 ; also on sheet 4 8
PTD14: R114.2 R116.1 R134.1 SJ5.1 ; also on sheet 4 8
PTD15: J9.14(B7) ; also on sheet 4
PTD16: J9.16(B8) ; also on sheet 4
PTD17: J5.3 ; also on sheet 4
PTD20: J8.22(B11) ; also on sheet 4
PTD21: J8.23(A12) ; also on sheet 4
PTD22: J8.24(B12) ; also on sheet 4
PTD23: J8.25(A13) ; also on sheet 4
PTD24: J8.26(B13) ; also on sheet 4
PTD26: J8.27(A14) ; also on sheet 4
PTD27: J8.28(B14) ; also on sheet 4
PTD28: J9.24(B12) ; also on sheet 4
PTD29: J9.6(B3) ; also on sheet 4
PTD30: J9.4(B2) ; also on sheet 4
PTD31: J9.1(A1) ; also on sheet 4
PTE0: J2.10 ; also on sheet 5
PTE1: J2.12 ; also on sheet 5
PTE2: J2.8 ; also on sheet 5
PTE3: J2.19 ; also on sheet 5 8
PTE4: SJ4.3 ; also on sheet 5
PTE5: SJ6.3 ; also on sheet 5
PTE6: J2.6 ; also on sheet 5
PTE8: J9.18(B9) ; also on sheet 5
PTE9: J9.15(A8) ; also on sheet 5
PTE10: J4.8(B4) ; also on sheet 5
PTE11: J3.11(A6) ; also on sheet 5
PTE12: J5.4 ; also on sheet 5
PTE14: J2.17 ; also on sheet 5 8
PTE15: J4.4(B2) ; also on sheet 5
PTE16: J4.2(B1) ; also on sheet 5
PTE17: J1.16(B8) ; also on sheet 5
PTE18: J2.2 ; also on sheet 5
PTE21: J1.12(B6) ; also on sheet 5
PTE22: J1.10(B5) ; also on sheet 5
PTE23: J1.6(B3) ; also on sheet 5
PTE26: J9.2(B1) ; also on sheet 5
TH-SDA: R132.2 U18.2(TH-SDA)
VPP: R125.2 R135.1 U18.5(VPP-MODE)
VREFH_MCU: C91.1 J2.16 ; also on sheet 5
N17904086: R122.2 R131.2 TP37.1(Pin1) U17.1(~{CS})
N17904088: R123.2 R129.2 TP38.1(Pin1) U17.3(IO2)
N17904199: R133.2 TP42.1(Pin1) U17.6(CLK)
N17939469: R128.2 TP40.1(Pin1) U17.2(DO/IO1)
N17939773: R126.2 TP41.1(Pin1) U17.5(DI/IO0)
N17940432: R124.2 R130.2 TP39.1(Pin1) U17.7(IO3)
N18039703: J4.10(B5) SJ6.2
N18039707: J4.12(B6) SJ4.2
N18097716: R111.2 R112.1 U16.2(BT_MODE)
N18097769: R113.2 R117.1 U16.3(SA0/SPI_MISO)
N18097844: R116.2 U16.5(SCL/SCLK)
N18097846: R118.1 U16.4(SDA/SPI_MOSI/SPI_DATA)
N18097864: R119.2 U16.7(~{SPI_CS}/WAKE_UP)
N18097884: R120.1 U16.8(INT1/MOT_DET)
N18101273: R121.1 U16.6(INT2/EXT_TRIG/BOOT_OUT)
N18114808: J7.6(B3) R149.2 SJ5.2
N18246149: J3.4(B2) R147.2
N18419338: J7.8(B4) R148.2 SJ3.2
N18488997: D13.A(ANODE) R138.2
N18489354: D1.2(CATHODE1) R141.1
N18489379: D1.3(CATHODE2) R143.1
N18489398: D1.4(CATHODE3) R144.1
N18625590: D1.1(ANODE) R142.2

Not connected (* = marked no-connect by the designer): J2 11* 13* 15*; J3 2(B1)*; J4 1(A1)* 3(A2)* 5(A3)* 7(A4)* 9(A5)* 11(A6)*

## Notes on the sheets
sheet 11
- ACCELEROMETER SENSOR
- I2C ADDRESS:  WR:30 RD:31
- QSPI FLASH
- MAGNETIC SWITCH
- Note:
  When MCXE31B is powered by 5V,
  the flash W25Q64JVSSIQ cannot be connected, it works only in 3.3V.
- 112MHZ
- Layout Notes:
  ======
  1.Length match routing with 50ohm resistance.
sheet 12
- SWITCH
- RGB LED
sheet 13
- LCD
- Arduino_D0/RX
- Arduino_D1/TX
- I2C_SDA
- I2C_SCL
- Arduino_D2           SimpleFOC2_ENC_I
- Arduino_D3/PWM       SimpleFOC2_PWM_A
- BLK
- D/C
- /INT
- /RST
- Arduino_D4           SimpleFOC1_ENC_I
- /WR
- /CS
- Arduino_D5/PWM       SimpleFOC1_PWM_C
- TE
- /RD
- Arduino_D6/PWM       SimpleFOC2_PWM_B
- D1
- D0
- Arduino_D7
- D3
- D2
- D5
- D7
- D4
- D6
- D9
- D8
- D11
- D10
- D13
- D12
- D15
- D14
- CAMERA
- Arduino_D8
- Arduino_D9/PWM       SimpleFOC2_PWM_C
- Arduino_D10/PWM/SS   SimpleFOC1_PWM_B
- Arduino_D11/PWM/MOSI SimpleFOC1_PWM_A
- Arduino_D12/MISO     SimpleFOC2_ENC_A
- Arduino_D13/SCK      SimpleFOC2_ENC_B
- Arduino_GND
- Arduino_AREF
- PWDN
- RST
- Arduino_D18/SDA
- D0
- D1
- Arduino_D19/SCL
- D2
- D3
- D4
- D6
- D5
- D7
- MCLK
- PCLK
- HS
- VS
- SDA
- SCL
- GND
- 3.3V
- MC_CUR_DCB
- MC_VOLT_DCB
- MC_BEMF_C
- MC_BEMF_B
- MC_BEMF_A
- RX_DAT
- RX_WCLK
- TX_WCLK
- MCLK
- RX_BCLK
- TX_DAT
- MIKRO BUS
- MC_ENC_I/SAI1_TX_FS
- TX_BCLK
- ARDUINO & FRDM
- socket board
- ANALOG
- RESET
- AN
  RST
  CS
  SCK
  MISO
  MOSI
  3V3
  GND
- PWM
  INT
  RX
  TX
  SCL
  SDA
  5V0
  GND
- INT
- PWM
- SPI_CS
- UART_RX
- SPI_SCK
- UART_TX
- SPI_MISO
- I2C_SCL
- MC_PWM_AT
- SPI_MOSI
- I2C_SDA
- MC_PWM_AB
- 3V3
- 5V
- MC_PWM_BB
- MC_PWM_BT
- GND
- GND
- MC_PWM_CT
- MC_PWM_CB
- MC_ENC_A
- MC_ENC_B
- CAD Note: PCB Edge Side
- 1. mikroBUS?logo positioned above the socket
  2. Pin names corresponding to the routing of the mainboard
  3. A line that encloses the socket on all sides except the top.
  4. A diagonal notch below the right-hand side pinout
       (serves as a guideline for add-on board insertion)
- Arduino_IOREF
- Arduino_RESET
- Arduino_3V3_OUT
- Arduino_5V0_OUT
- Arduino_GND
- Arduino_GND
- Arduino_VIN
- PMOD
- Arduino_A0  SimpleFOC1_CUR_A
- Arduino_A1  SimpleFOC2_CUR_A
- Arduino_A2  SimpleFOC1_CUR_B
- Arduino_A3  SimpleFOC2_CUR_B
- Arduino_A4/SDA   SimpleFOC1_ENC_B
- Arduino_A5/SCL   SimpleFOC1_ENC_A
- Shield Boards:
  1. Arduino_: Arduino UNO R3
  2. Sensor:FRDM-STBC-AGM01, FRDM-STBC-AGM04, FRDM-FXS-MULT2-B
  3. NFC: OM5577, OM5578
  4. WiFi: Mikroe Click connections
  5. Motor control: FRDM-MC-LVBLDC, FRDM-MC-LVPMSM, Arduino-SimpleFOCShield
  6. Audio: ARD-AUDIO-DA7212
- I2C_SDA/SPI_CS3
- SPI_SCK
- I2C_SCL/SPI_CS2
- SPI_SIN
- RESET
- SPI_SOUT
- INT
- SPI_CS0
- 5VDC VR
  SUPPORT
- IN
- OUT
sheet 14
- REF DES
- JUMPER
- PAGE NAME
- J10,JP1,JP2
- 1-2
- 03 POWER
- JP3,JP4,JP5,JP6
- OPEN
- 07 MCU_LINK
- REF DES
- ASSY_OPT
- PAGE NAME
- D3,J11,J12
- DNP
- 03 POWER
- R13
- DNP
- 05 MCU_C
- C40,C41,R22,R25,U3
- DNP
- 07 MCU_LINK
- D8,D9,J15,J21,R47,R50,R52
- DNP
- 08 MCU_LINK_DEBUG
- C56,C59,C60,C61,C62,R83,R84,
  R85,R86,R87,R88,R89,R91,R92
- DNP
- 09 ETHERNET
- C71,C74,C77,R93,R99,R105
- DNP
- 10 CAN
- R111,R113,R121,R126,R127,
  R128,R129,R130,R131,R133,R135
- DNP
- 11 QSPI FLASH & SENSOR
- C94,C95,C96,C97,J7,J20
- DNP
- 13 HEADERS
- REF DES
- SHORT(DEFAULT)
- PAGE NAME
- SJ1,SJ2
- 1-2
- 10 CAN
- SJ3,SJ4,SJ5,SJ6
- 1-2
- 13 HEADERS
